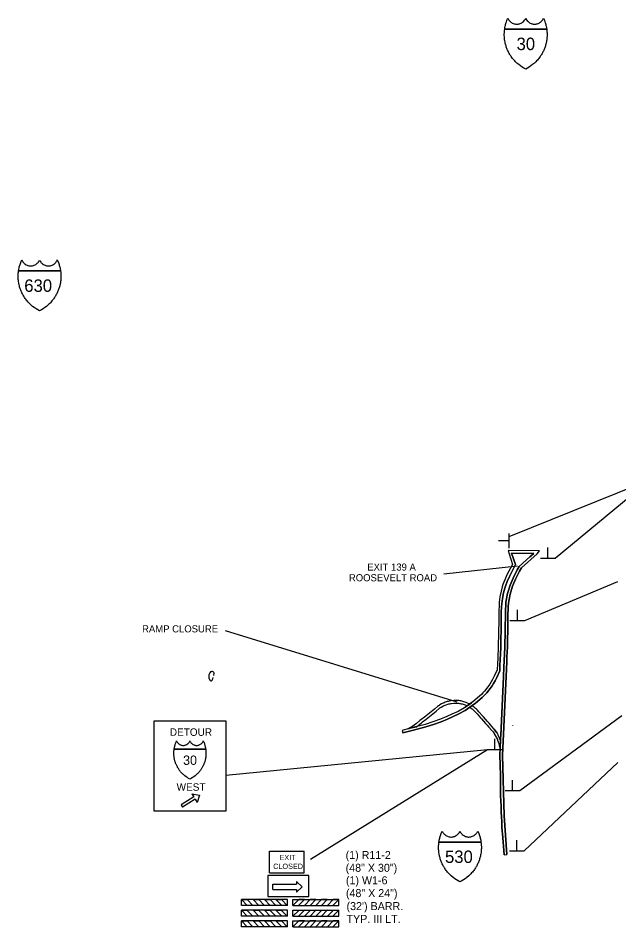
# Model space of a CAD drawing. Extents: x 759664 to 915266, y 962354 to 1064674.
# Drawn here: x 759664 to 827291, y 962431 to 1064674 of the extents above; entities that cross this region are included whole.
import ezdxf

# ---------------------------------------------------------------- set-up
doc = ezdxf.new("R2010")
doc.units = 0
for name, color, linetype in [('G-ANNO-TEXT', 7, 'Continuous'), ('Level 14', 7, 'Continuous'), ('Level 16', 7, 'Continuous'), ('Level 50', 7, 'Continuous'), ('Level 59', 7, 'Continuous'), ('Level 61', 7, 'Continuous'), ('Level 62', 7, 'Continuous'), ('R_Draft', 7, 'Continuous')]:
    doc.layers.add(name, color=color, linetype=linetype)

msp = doc.modelspace()

# ---------------------------------------------------------------- linework, layer by layer
at = {"layer": 'Level 14'}
for points in [[(814438, 1063430), (814455, 1063543), (814473, 1063643), (814500, 1063772), (814519, 1063856), (814544, 1063956), (814577, 1064073), (814607, 1064171), (814641, 1064272), (814686, 1064396), (814733, 1064513), (814771, 1064603), (814804, 1064674), (814838, 1064597), (814879, 1064524), (814923, 1064457), (814980, 1064383), (815026, 1064332), (815082, 1064278), (815139, 1064230), (815201, 1064185), (815299, 1064126), (815400, 1064079), (815491, 1064047), (815581, 1064024), (815677, 1064008), (815790, 1064001), (815864, 1064002), (815948, 1064010), (816024, 1064023), (816105, 1064043), (816186, 1064070), (816295, 1064118), (816371, 1064160), (816459, 1064220), (816543, 1064291), (816604, 1064353), (816674, 1064438), (816732, 1064525), (816766, 1064585), (816803, 1064665)], [(816803, 1064665), (816841, 1064585), (816875, 1064525), (816932, 1064438), (817003, 1064353), (817064, 1064291), (817148, 1064220), (817236, 1064160), (817311, 1064118), (817421, 1064070), (817502, 1064043), (817583, 1064023), (817658, 1064010), (817743, 1064002), (817817, 1064001), (817929, 1064008), (818026, 1064024), (818116, 1064047), (818207, 1064079), (818308, 1064126), (818406, 1064185), (818468, 1064230), (818524, 1064278), (818581, 1064332), (818626, 1064383), (818684, 1064457), (818728, 1064524), (818768, 1064597), (818803, 1064674), (818835, 1064603), (818874, 1064513), (818920, 1064396), (818965, 1064272), (818999, 1064171), (819029, 1064073), (819062, 1063956), (819088, 1063856), (819107, 1063772), (819134, 1063643), (819152, 1063543), (819169, 1063430)], [(816803, 1058949), (816596, 1059059), (816414, 1059169), (816213, 1059304), (816026, 1059446), (815821, 1059621), (815745, 1059692), (815658, 1059777), (815577, 1059860), (815489, 1059957), (815403, 1060057), (815330, 1060146), (815252, 1060248), (815181, 1060347), (815119, 1060437), (815065, 1060521), (815021, 1060593), (814961, 1060694), (814915, 1060776), (814865, 1060873), (814815, 1060973), (814773, 1061066), (814734, 1061155), (814693, 1061255), (814658, 1061348), (814623, 1061445), (814590, 1061546), (814559, 1061650), (814532, 1061749), (814509, 1061843), (814489, 1061927), (814476, 1061989), (814454, 1062109), (814432, 1062248), (814418, 1062364), (814407, 1062486), (814401, 1062585), (814396, 1062710), (814395, 1062827), (814397, 1062958), (814401, 1063043), (814406, 1063122), (814409, 1063171), (814421, 1063299), (814438, 1063430)], [(819169, 1063430), (814438, 1063430)], [(814438, 1063430), (819169, 1063430)], [(819169, 1063430), (819185, 1063299), (819197, 1063171), (819201, 1063122), (819206, 1063043), (819209, 1062958), (819212, 1062827), (819211, 1062710), (819206, 1062585), (819200, 1062486), (819189, 1062364), (819174, 1062248), (819153, 1062109), (819130, 1061989), (819117, 1061927), (819098, 1061843), (819075, 1061749), (819048, 1061650), (819017, 1061546), (818983, 1061445), (818949, 1061348), (818914, 1061255), (818873, 1061155), (818834, 1061066), (818791, 1060973), (818742, 1060873), (818691, 1060776), (818645, 1060694), (818586, 1060593), (818542, 1060521), (818487, 1060437), (818426, 1060347), (818355, 1060248), (818276, 1060146), (818204, 1060057), (818118, 1059957), (818029, 1059860), (817949, 1059777), (817862, 1059692), (817786, 1059621), (817581, 1059446), (817394, 1059304), (817193, 1059169), (817011, 1059059), (816803, 1058949)], [(759707, 1036228), (759725, 1036341), (759742, 1036441), (759769, 1036570), (759788, 1036654), (759814, 1036754), (759847, 1036871), (759877, 1036969), (759911, 1037070), (759956, 1037194), (760002, 1037310), (760041, 1037401), (760073, 1037472), (760108, 1037395), (760148, 1037322), (760192, 1037255), (760250, 1037180), (760295, 1037130), (760352, 1037075), (760408, 1037028), (760470, 1036983), (760568, 1036924), (760669, 1036877), (760760, 1036845), (760850, 1036822), (760947, 1036806), (761059, 1036798), (761133, 1036800), (761218, 1036808), (761293, 1036821), (761374, 1036840), (761455, 1036867), (761565, 1036916), (761640, 1036958), (761728, 1037018), (761812, 1037089), (761873, 1037151), (761944, 1037236), (762001, 1037322), (762035, 1037383), (762073, 1037463)], [(762073, 1037463), (762110, 1037383), (762144, 1037322), (762202, 1037236), (762272, 1037151), (762333, 1037089), (762417, 1037018), (762505, 1036958), (762581, 1036916), (762690, 1036867), (762771, 1036840), (762852, 1036821), (762928, 1036808), (763012, 1036800), (763086, 1036798), (763199, 1036806), (763295, 1036822), (763385, 1036845), (763476, 1036877), (763577, 1036924), (763675, 1036983), (763737, 1037028), (763794, 1037075), (763850, 1037130), (763896, 1037180), (763953, 1037255), (763997, 1037322), (764038, 1037395), (764072, 1037472), (764105, 1037401), (764143, 1037310), (764190, 1037194), (764235, 1037070), (764269, 1036969), (764299, 1036871), (764332, 1036754), (764357, 1036654), (764377, 1036570), (764403, 1036441), (764421, 1036341), (764438, 1036228)], [(762073, 1031746), (761865, 1031857), (761683, 1031967), (761482, 1032102), (761295, 1032244), (761090, 1032418), (761014, 1032490), (760927, 1032575), (760847, 1032658), (760758, 1032754), (760672, 1032855), (760600, 1032944), (760521, 1033046), (760450, 1033144), (760389, 1033235), (760334, 1033318), (760290, 1033390), (760231, 1033491), (760185, 1033574), (760134, 1033671), (760085, 1033771), (760042, 1033863), (760003, 1033953), (759962, 1034053), (759927, 1034146), (759893, 1034243), (759859, 1034344), (759828, 1034447), (759801, 1034546), (759778, 1034640), (759759, 1034724), (759746, 1034786), (759723, 1034907), (759702, 1035046), (759687, 1035162), (759676, 1035284), (759670, 1035383), (759665, 1035508), (759664, 1035625), (759666, 1035755), (759670, 1035841), (759675, 1035920), (759679, 1035969), (759691, 1036097), (759707, 1036228)], [(764438, 1036228), (759707, 1036228)], [(759707, 1036228), (764438, 1036228)], [(764438, 1036228), (764455, 1036097), (764467, 1035969), (764470, 1035920), (764475, 1035841), (764479, 1035755), (764481, 1035625), (764480, 1035508), (764475, 1035383), (764469, 1035284), (764458, 1035162), (764444, 1035046), (764422, 1034907), (764400, 1034786), (764387, 1034724), (764368, 1034640), (764344, 1034546), (764317, 1034447), (764286, 1034344), (764253, 1034243), (764218, 1034146), (764183, 1034053), (764142, 1033953), (764103, 1033863), (764061, 1033771), (764011, 1033671), (763961, 1033574), (763915, 1033491), (763855, 1033390), (763811, 1033318), (763757, 1033235), (763695, 1033144), (763624, 1033046), (763546, 1032944), (763473, 1032855), (763387, 1032754), (763299, 1032658), (763218, 1032575), (763131, 1032490), (763055, 1032418), (762850, 1032244), (762663, 1032102), (762462, 1031967), (762280, 1031857), (762073, 1031746)], [(777229, 982416), (777242, 982501), (777255, 982576), (777275, 982672), (777290, 982735), (777309, 982810), (777333, 982898), (777356, 982972), (777381, 983047), (777415, 983141), (777450, 983228), (777479, 983296), (777503, 983349), (777529, 983292), (777560, 983237), (777593, 983186), (777636, 983130), (777670, 983093), (777712, 983052), (777755, 983016), (777801, 982982), (777875, 982938), (777950, 982903), (778019, 982879), (778086, 982861), (778159, 982849), (778243, 982844), (778298, 982845), (778362, 982851), (778418, 982861), (778479, 982875), (778540, 982896), (778622, 982932), (778679, 982964), (778745, 983009), (778808, 983062), (778854, 983108), (778906, 983172), (778950, 983237), (778975, 983282), (779003, 983342)], [(779003, 983342), (779031, 983282), (779056, 983237), (779100, 983172), (779152, 983108), (779198, 983062), (779262, 983009), (779327, 982964), (779384, 982932), (779466, 982896), (779527, 982875), (779588, 982861), (779644, 982851), (779708, 982845), (779763, 982844), (779847, 982849), (779920, 982861), (779987, 982879), (780056, 982903), (780131, 982938), (780205, 982982), (780251, 983016), (780294, 983052), (780336, 983093), (780370, 983130), (780413, 983186), (780447, 983237), (780477, 983292), (780503, 983349), (780527, 983296), (780556, 983228), (780591, 983141), (780625, 983047), (780650, 982972), (780673, 982898), (780697, 982810), (780716, 982735), (780731, 982672), (780751, 982576), (780764, 982501), (780777, 982416)], [(779003, 979055), (778848, 979138), (778711, 979220), (778560, 979322), (778420, 979428), (778266, 979559), (778209, 979612), (778144, 979676), (778083, 979738), (778017, 979811), (777952, 979886), (777898, 979953), (777840, 980030), (777786, 980103), (777740, 980171), (777699, 980234), (777666, 980288), (777621, 980364), (777587, 980426), (777549, 980498), (777512, 980573), (777480, 980643), (777451, 980710), (777420, 980785), (777394, 980854), (777368, 980927), (777343, 981003), (777320, 981081), (777300, 981155), (777282, 981225), (777268, 981288), (777258, 981335), (777241, 981425), (777225, 981530), (777214, 981616), (777206, 981708), (777201, 981782), (777198, 981876), (777197, 981964), (777198, 982062), (777201, 982126), (777205, 982185), (777207, 982222), (777217, 982318), (777229, 982416)], [(780777, 982416), (777229, 982416)], [(777229, 982416), (780777, 982416)], [(780777, 982416), (780789, 982318), (780799, 982222), (780801, 982185), (780805, 982126), (780808, 982062), (780809, 981964), (780809, 981876), (780805, 981782), (780800, 981708), (780792, 981616), (780781, 981530), (780765, 981425), (780748, 981335), (780738, 981288), (780724, 981225), (780707, 981155), (780686, 981081), (780663, 981003), (780638, 980927), (780612, 980854), (780586, 980785), (780555, 980710), (780526, 980643), (780494, 980573), (780457, 980498), (780419, 980426), (780385, 980364), (780340, 980288), (780307, 980234), (780266, 980171), (780220, 980103), (780166, 980030), (780108, 979953), (780054, 979886), (779989, 979811), (779923, 979738), (779862, 979676), (779797, 979612), (779740, 979559), (779586, 979428), (779446, 979322), (779295, 979220), (779158, 979138), (779003, 979055)], [(807040, 971965), (807058, 972078), (807075, 972178), (807102, 972307), (807121, 972391), (807147, 972491), (807180, 972608), (807210, 972706), (807244, 972807), (807289, 972931), (807335, 973048), (807374, 973138), (807406, 973210), (807441, 973133), (807481, 973059), (807525, 972992), (807583, 972918), (807628, 972868), (807685, 972813), (807742, 972765), (807803, 972720), (807901, 972662), (808002, 972615), (808093, 972582), (808183, 972559), (808280, 972543), (808392, 972536), (808466, 972537), (808551, 972545), (808626, 972558), (808707, 972578), (808788, 972605), (808898, 972653), (808973, 972695), (809061, 972755), (809145, 972826), (809207, 972888), (809277, 972973), (809335, 973060), (809369, 973121), (809406, 973201)], [(809406, 973201), (809443, 973121), (809477, 973060), (809535, 972973), (809605, 972888), (809666, 972826), (809751, 972755), (809838, 972695), (809914, 972653), (810023, 972605), (810105, 972578), (810185, 972558), (810261, 972545), (810346, 972537), (810419, 972536), (810532, 972543), (810628, 972559), (810718, 972582), (810809, 972615), (810910, 972662), (811008, 972720), (811070, 972765), (811127, 972813), (811183, 972868), (811229, 972918), (811286, 972992), (811330, 973059), (811371, 973133), (811406, 973210), (811438, 973138), (811476, 973048), (811523, 972931), (811568, 972807), (811602, 972706), (811632, 972608), (811665, 972491), (811690, 972391), (811710, 972307), (811736, 972178), (811754, 972078), (811771, 971965)], [(809406, 967484), (809199, 967594), (809016, 967704), (808816, 967840), (808628, 967981), (808424, 968156), (808347, 968227), (808260, 968312), (808180, 968395), (808092, 968492), (808005, 968592), (807933, 968681), (807855, 968783), (807783, 968882), (807722, 968972), (807668, 969056), (807623, 969128), (807564, 969229), (807518, 969312), (807467, 969408), (807418, 969508), (807375, 969601), (807336, 969690), (807295, 969790), (807260, 969883), (807226, 969980), (807193, 970081), (807162, 970185), (807134, 970284), (807111, 970378), (807092, 970462), (807079, 970524), (807056, 970644), (807035, 970784), (807020, 970899), (807009, 971021), (807003, 971120), (806999, 971246), (806997, 971363), (807000, 971493), (807003, 971578), (807008, 971657), (807012, 971706), (807024, 971834), (807040, 971965)], [(811771, 971965), (807040, 971965)], [(807040, 971965), (811771, 971965)], [(811771, 971965), (811788, 971834), (811800, 971706), (811804, 971657), (811808, 971578), (811812, 971493), (811814, 971363), (811813, 971246), (811808, 971120), (811802, 971021), (811792, 970899), (811777, 970784), (811755, 970644), (811733, 970524), (811720, 970462), (811701, 970378), (811677, 970284), (811650, 970185), (811619, 970081), (811586, 969980), (811552, 969883), (811516, 969790), (811475, 969690), (811437, 969601), (811394, 969508), (811345, 969408), (811294, 969312), (811248, 969229), (811189, 969128), (811144, 969056), (811090, 968972), (811028, 968882), (810957, 968783), (810879, 968681), (810807, 968592), (810720, 968492), (810632, 968395), (810551, 968312), (810465, 968227), (810388, 968156), (810183, 967981), (809996, 967840), (809795, 967704), (809613, 967594), (809406, 967484)]]:
    msp.add_lwpolyline(points, dxfattribs=at)
at = {"layer": 'Level 16'}
for p, q in [((810146, 987328), (810229, 987288)), ((810229, 987288), (810431, 987422)), ((810435, 987519), (810270, 987599)), ((810431, 987422), (810500, 987472)), ((810505, 987480), (810435, 987519)), ((810766, 987323), (810507, 987134)), ((813248, 984676), (813218, 984712)), ((813248, 984676), (813587, 984216)), ((813234, 984209), (813614, 983507)), ((813234, 984209), (813577, 983575)), ((813723, 983971), (813904, 983587)), ((813974, 983412), (813904, 983587)), ((813931, 982480), (813974, 983412))]:
    msp.add_line(p, q, dxfattribs=at)
for points in [[(810270, 987599), (810108, 987669), (809966, 987722), (809851, 987759), (809734, 987792), (809617, 987821), (809498, 987846), (809379, 987866), (809258, 987881), (809033, 987899), (808925, 987901), (808818, 987900), (808711, 987896), (808432, 987871), (808309, 987852), (808189, 987828), (808070, 987800), (807951, 987767), (807731, 987693), (807625, 987651), (807521, 987607), (807419, 987558), (807319, 987506), (807138, 987405), (807053, 987353), (806975, 987302), (806887, 987238), (806524, 986941), (806160, 986637), (805773, 986318), (805424, 986035), (805016, 985720), (804889, 985629), (804508, 985325), (804233, 985110), (804084, 985009), (803541, 984698)], [(804502, 984950), (804692, 985092), (805068, 985392), (805193, 985481), (805609, 985801), (805962, 986088), (806350, 986408), (806713, 986712), (807069, 987002), (807145, 987057), (807213, 987102), (807288, 987148), (807460, 987244), (807551, 987292), (807644, 987335), (807738, 987376), (807833, 987413), (808038, 987482), (808144, 987512), (808252, 987537), (808360, 987559), (808468, 987575), (808730, 987599), (808826, 987603), (808923, 987604), (809018, 987602), (809227, 987585), (809335, 987571), (809443, 987553), (809551, 987531), (809658, 987505), (809764, 987475), (809868, 987441), (809997, 987393), (810146, 987328)], [(810500, 987472), (810505, 987480)], [(810507, 987134), (810584, 987087), (810674, 987026), (810761, 986963), (810862, 986878), (810962, 986787), (811058, 986695), (811153, 986599), (811322, 986407)], [(811544, 986605), (811371, 986802), (811267, 986907), (811165, 987005), (811057, 987102), (810945, 987197), (810845, 987269), (810766, 987323)], [(811322, 986407), (811727, 985956), (811829, 985845), (812286, 985321), (812454, 985136), (812612, 984951), (812993, 984516)], [(813218, 984712), (812837, 985146), (812677, 985333), (812508, 985519), (812051, 986045), (811946, 986156), (811544, 986605)], [(803541, 984698), (803958, 984808), (804502, 984950)], [(804502, 984950), (804502, 984950)], [(813587, 984216), (813555, 984260), (813248, 984676)], [(812993, 984516), (813086, 984409), (813130, 984354), (813212, 984242)], [(813212, 984242), (813234, 984209)], [(813723, 983971), (813689, 984040), (813616, 984169), (813587, 984216)], [(813904, 983587), (813888, 983623), (813756, 983902), (813723, 983971)], [(813577, 983575), (813582, 983578)], [(813582, 983578), (813614, 983507), (813646, 983437)], [(813646, 983437), (813723, 983234), (813781, 983054), (813833, 982850), (813858, 982731), (813897, 982482)], [(813897, 982482), (813931, 982480)]]:
    msp.add_lwpolyline(points, dxfattribs=at)
at = {"layer": 'Level 50'}
msp.add_lwpolyline([(781685, 990714), (781719, 990960), (781696, 991062), (781625, 991120), (781558, 991147), (781460, 991152), (781376, 991136), (781324, 991107), (781252, 991028), (781138, 990780), (781114, 990569), (781141, 990394), (781289, 990155), (781356, 990125), (781402, 990126), (781488, 990183), (781580, 990336), (781619, 990491)], dxfattribs=at)
at = {"layer": 'Level 59'}
for p, q in [((814928, 1005035), (814928, 1006698)), ((814928, 1005866), (813731, 1005866)), ((819293, 1003919), (819293, 1005116)), ((818090, 1004417), (816323, 1002843)), ((816323, 1002843), (818090, 1004417)), ((818461, 1003919), (820124, 1003919)), ((815867, 996896), (815867, 998093)), ((815035, 996896), (816698, 996896)), ((802911, 984531), (802987, 984243)), ((802911, 984531), (802987, 984243)), ((813343, 982375), (813343, 983573)), ((812511, 982375), (814174, 982375)), ((815307, 977752), (815307, 978949)), ((814476, 977752), (816139, 977752)), ((779448, 977040), (778001, 976165)), ((779603, 976784), (778157, 975908)), ((778001, 976165), (778157, 975908)), ((815798, 970984), (815798, 972181)), ((814369, 970526), (814690, 970556)), ((814369, 970526), (814690, 970556)), ((814966, 970984), (816629, 970984))]:
    msp.add_line(p, q, dxfattribs=at)
for points in [[(813897, 981735), (813974, 983412), (813984, 983643), (813999, 983951), (814304, 990583), (814353, 991642), (814447, 993849), (814514, 997780), (814585, 998978), (814752, 999937), (814778, 1000054), (815044, 1000878), (815382, 1001668), (815854, 1002588), (816060, 1002981), (817288, 1004068)], [(817288, 1004068), (816060, 1002981), (815854, 1002588), (815382, 1001668), (815044, 1000878), (814778, 1000054), (814752, 999937), (814585, 998978), (814514, 997780), (814447, 993849), (814353, 991642), (814304, 990583), (813999, 983951), (813984, 983643), (813974, 983412), (813897, 981735)], [(818090, 1004417), (818361, 1004756), (814825, 1004788), (814949, 1004413), (815312, 1003208)], [(818090, 1004417), (818361, 1004756), (814825, 1004788), (814949, 1004413), (815312, 1003208)], [(817288, 1004068), (817738, 1004441), (815197, 1004489), (815657, 1003193)], [(815657, 1003193), (815197, 1004489), (817738, 1004441), (817288, 1004068)], [(815312, 1003208), (814694, 1002030), (814446, 1001467), (814245, 1000944), (814166, 1000703), (814029, 1000196), (813906, 999555), (813833, 998947), (813820, 998625), (813782, 997961), (813774, 996951), (813715, 994026), (813658, 992643), (813630, 992034), (813586, 991344), (813269, 990642), (813080, 990269), (812918, 989985), (812757, 989732), (812545, 989426), (812152, 988941), (811988, 988760), (811813, 988580), (811613, 988384), (810862, 987760), (810489, 987489)], [(815312, 1003208), (814694, 1002030), (814446, 1001467), (814245, 1000944), (814166, 1000703), (814029, 1000196), (813906, 999555), (813833, 998947), (813820, 998625), (813782, 997961), (813774, 996951), (813715, 994026), (813658, 992643), (813630, 992034), (813586, 991344), (813269, 990642), (813080, 990269), (812918, 989985), (812757, 989732), (812545, 989426), (812152, 988941), (811988, 988760), (811813, 988580), (811613, 988384), (810862, 987760), (810678, 987627)], [(815657, 1003193), (814971, 1001864), (814723, 1001301), (814523, 1000778), (814443, 1000537), (814306, 1000030), (814184, 999389), (814111, 998781), (814097, 998459), (814060, 997795), (814051, 996785), (813993, 993860), (813936, 992477), (813908, 991867), (813878, 991229), (813546, 990476), (813358, 990103), (813195, 989819), (813034, 989566), (812822, 989260), (812429, 988775), (812265, 988594), (812091, 988414), (811891, 988218), (811139, 987594), (810766, 987323)], [(810766, 987323), (811139, 987594), (811891, 988218), (812091, 988414), (812265, 988594), (812429, 988775), (812822, 989260), (813034, 989566), (813195, 989819), (813358, 990103), (813546, 990476), (813878, 991229), (813908, 991867), (813936, 992477), (813993, 993860), (814051, 996785), (814060, 997795), (814097, 998459), (814111, 998781), (814184, 999389), (814306, 1000030), (814443, 1000537), (814523, 1000778), (814723, 1001301), (814971, 1001864), (815657, 1003193)], [(816323, 1002843), (816119, 1002451), (815651, 1001540), (815322, 1000772), (815043, 999877), (814927, 999273), (814869, 998834), (814849, 998422), (814806, 997331), (814783, 995757), (814764, 994771), (814745, 993841), (814734, 993460), (814698, 992684), (814677, 992230), (814302, 984091), (814194, 981742)], [(814194, 981742), (814302, 984091), (814677, 992230), (814698, 992684), (814734, 993460), (814745, 993841), (814764, 994771), (814783, 995757), (814806, 997331), (814849, 998422), (814869, 998834), (814927, 999273), (815043, 999877), (815322, 1000772), (815651, 1001540), (816119, 1002451), (816323, 1002843)], [(810690, 987610), (810431, 987422), (809906, 987074), (809217, 986668), (808504, 986343), (807939, 986088), (807212, 985802), (806364, 985498), (805501, 985211), (803958, 984808), (802911, 984531)], [(810229, 987288), (809906, 987074), (809217, 986668), (808504, 986343), (807939, 986088), (807212, 985802), (806364, 985498), (805501, 985211), (803958, 984808), (802911, 984531)], [(810766, 987323), (810507, 987134), (809982, 986786), (809293, 986380), (808580, 986055), (808015, 985800), (807289, 985515), (806440, 985210), (805577, 984923), (804034, 984521), (802987, 984243)], [(802987, 984243), (804034, 984521), (805577, 984923), (806440, 985210), (807289, 985515), (808015, 985800), (808580, 986055), (809293, 986380), (809982, 986786), (810507, 987134), (810766, 987323)], [(810606, 987574), (810489, 987489), (810229, 987288)], [(810678, 987627), (810606, 987574)], [(814369, 970526), (814176, 972939), (814161, 973153), (814130, 973726), (814109, 974221), (814068, 974890), (814047, 975305), (814027, 976017), (813977, 977197), (813950, 979491), (813897, 981735)], [(813897, 981735), (813950, 979491), (813977, 977197), (814027, 976017), (814047, 975305), (814068, 974890), (814109, 974221), (814130, 973726), (814161, 973153), (814176, 972939), (814369, 970526)], [(814194, 981742), (814365, 974907), (814690, 970556)], [(814690, 970556), (814365, 974907), (814194, 981742)]]:
    msp.add_lwpolyline(points, dxfattribs=at)
at = {"layer": 'Level 61'}
for p, q in [((815349, 985063), (815346, 985066)), ((787978, 968507), (787978, 970939)), ((787978, 970939), (791870, 970939)), ((791870, 968507), (791870, 970939)), ((787978, 968507), (791870, 968507)), ((788349, 966641), (788349, 967228)), ((789980, 965490), (784817, 965490)), ((784817, 964842), (784817, 965490)), ((789980, 964844), (789980, 965490)), ((790590, 964844), (790590, 965490)), ((790590, 965490), (795753, 965490)), ((795753, 964842), (795753, 965490)), ((789980, 964830), (784817, 964830)), ((789980, 964288), (784817, 964288)), ((784817, 963642), (784817, 964288)), ((789980, 963642), (789980, 964288)), ((790590, 964830), (795753, 964830)), ((790590, 964288), (795753, 964288)), ((790590, 963642), (790590, 964288)), ((795753, 963642), (795753, 964288)), ((789980, 963642), (784817, 963642)), ((790590, 963642), (795753, 963642)), ((784817, 962444), (784817, 963091)), ((789980, 963091), (784817, 963091)), ((789980, 962431), (784817, 962431)), ((789980, 962444), (789980, 963091)), ((790590, 963091), (795753, 963091)), ((790590, 962444), (790590, 963091)), ((790590, 962431), (795753, 962431)), ((795753, 962444), (795753, 963091))]:
    msp.add_line(p, q, dxfattribs=at)
for points in [[(784817, 965490), (785452, 965488), (786097, 964844), (785464, 964844)], [(786107, 965490), (786742, 965488), (787387, 964844), (786754, 964844)], [(787397, 965490), (788032, 965488), (788677, 964844), (788044, 964844)], [(788687, 965490), (789322, 965488), (789967, 964844), (789334, 964844)], [(791883, 965490), (791248, 965488), (790604, 964844), (791237, 964844)], [(793173, 965490), (792538, 965488), (791894, 964844), (792527, 964844)], [(794463, 965490), (793828, 965488), (793184, 964844), (793817, 964844)], [(795753, 965490), (795118, 965488), (794474, 964844), (795107, 964844)], [(784817, 964288), (785452, 964286), (786097, 963642), (785464, 963642)], [(786107, 964288), (786742, 964286), (787387, 963642), (786754, 963642)], [(787397, 964288), (788032, 964286), (788677, 963642), (788044, 963642)], [(788687, 964288), (789322, 964286), (789967, 963642), (789334, 963642)], [(791883, 964288), (791248, 964286), (790604, 963642), (791237, 963642)], [(793173, 964288), (792538, 964286), (791894, 963642), (792527, 963642)], [(794463, 964288), (793828, 964286), (793184, 963642), (793817, 963642)], [(795753, 964288), (795118, 964286), (794474, 963642), (795107, 963642)], [(784817, 963091), (785452, 963089), (786097, 962444), (785464, 962444)], [(786107, 963091), (786742, 963089), (787387, 962444), (786754, 962444)], [(787397, 963091), (788032, 963089), (788677, 962444), (788044, 962444)], [(788687, 963091), (789322, 963089), (789967, 962444), (789334, 962444)], [(791883, 963091), (791248, 963089), (790604, 962444), (791237, 962444)], [(793173, 963091), (792538, 963089), (791894, 962444), (792527, 962444)], [(794463, 963091), (793828, 963089), (793184, 962444), (793817, 962444)], [(795753, 963091), (795118, 963089), (794474, 962444), (795107, 962444)]]:
    msp.add_lwpolyline(points, close=True, dxfattribs=at)
at = {"layer": 'Level 62'}
for p, q in [((779222, 977414), (780075, 977245)), ((779222, 977414), (779448, 977040)), ((779603, 976784), (779829, 976410)), ((780075, 977245), (779829, 976410)), ((788349, 967228), (790982, 967228)), ((790982, 967521), (791625, 966935)), ((790982, 967521), (790982, 967228)), ((788349, 966641), (790982, 966641)), ((791625, 966935), (790982, 966348)), ((790982, 966641), (790982, 966348))]:
    msp.add_line(p, q, dxfattribs=at)
for points in [[(783043, 985611), (783043, 975428), (774963, 975428), (774963, 985611)], [(792377, 968192), (787761, 968192), (787761, 965831), (792377, 965831)]]:
    msp.add_lwpolyline(points, close=True, dxfattribs=at)
at = {"layer": 'R_Draft'}
for p, q in [((814928, 1006343), (830806, 1012746)), ((820124, 1003919), (830806, 1012746)), ((807593, 1002148), (815891, 1003051)), ((816698, 996896), (827182, 1001296)), ((782988, 995784), (809065, 987751)), ((816139, 977752), (827634, 986199)), ((783043, 979478), (812511, 982375)), ((792576, 970033), (812511, 982375)), ((816629, 970984), (827168, 980937))]:
    msp.add_line(p, q, dxfattribs=at)

# ---------------------------------------------------------------- texts
at = {"layer": 'G-ANNO-TEXT'}
for s, height, p in [('30', 1402.1, (815775, 1061081)), ('630', 1402.1, (760353, 1033879)), ('30', 1051.6, (778232, 980654)), ('530', 1402.1, (807721, 969617))]:
    msp.add_text(s, height=height, dxfattribs=at).set_placement(p)
at = {"layer": 'Level 61'}
for s, height, p in [('EXIT', 589.2, (789093, 969933)), ('CLOSED', 592.1, (788371, 968946))]:
    msp.add_text(s, height=height, dxfattribs=at).set_placement(p)
at = {"layer": 'Level 62'}
for s, height, p in [('DETOUR', 841.8, (776739, 983922)), ('WEST', 841.8, (777502, 977740)), ('(1) R11-2', 900.3, (796532, 970064)), ('(48" X 30")', 900.31, (796532, 968623)), ('(1) W1-6', 900.3, (796566, 967214)), ('(48" X 24")', 900.31, (796566, 965774)), ("(32') BARR.", 900.31, (796633, 964314)), ('TYP. III LT.', 900.31, (796633, 962873))]:
    msp.add_text(s, height=height, dxfattribs=at).set_placement(p)
at = {"layer": 'R_Draft'}
for s, p in [('EXIT 139 A', (798966, 1002512)), ('ROOSEVELT ROAD', (796899, 1001312)), ('RAMP CLOSURE', (773613, 995559))]:
    msp.add_text(s, height=800, dxfattribs=at).set_placement(p)

doc.saveas('drawing.dxf')
